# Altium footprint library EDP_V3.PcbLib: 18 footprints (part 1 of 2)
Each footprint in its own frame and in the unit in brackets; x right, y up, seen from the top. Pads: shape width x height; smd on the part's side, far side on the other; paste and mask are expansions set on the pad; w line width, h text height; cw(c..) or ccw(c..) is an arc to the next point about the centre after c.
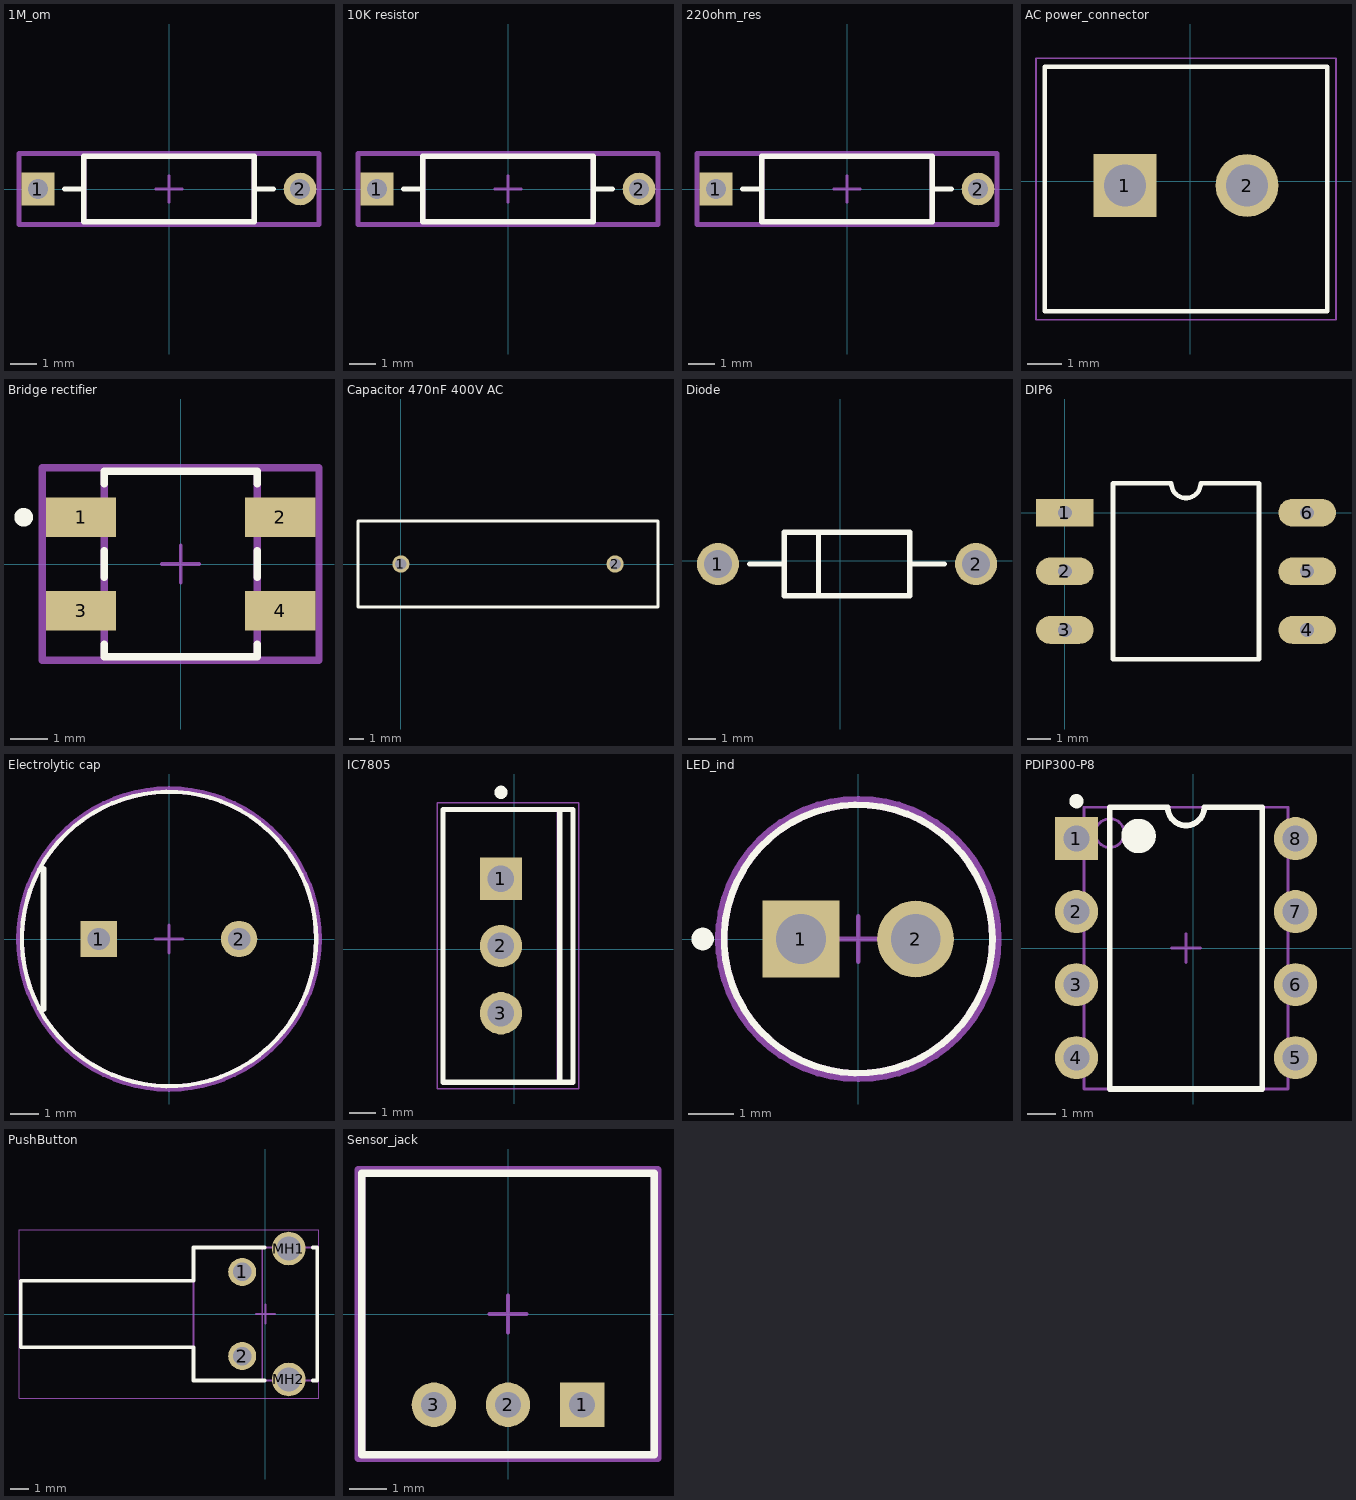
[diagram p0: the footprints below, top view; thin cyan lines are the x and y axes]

## 1M_om [mm]
pads (2):
  rect 1.25x1.25 hole 0.75 paste-2539.97 mask+0: 1(-5,0)
  round 1.25 hole 0.75 paste-2539.97 mask+0: 2(5,0)
Top Overlay:
  lines w0.2: -3.975,0 -3.25,0 ; 3.25,0 3.975,0 ; -3.25,-1.25 3.25,-1.25 3.25,1.25 -3.25,1.25 -3.25,-1.25
Top 3D Body:
  lines w0.2: -3.25,-1.25 3.25,-1.25 3.25,1.25 -3.25,1.25 -3.25,-1.25
Board:
  lines w0.2: -5.725,-1.35 5.725,-1.35 5.725,1.35 -5.725,1.35 -5.725,-1.35
Top Assembly:
  lines w0.2: -5.725,-1.35 5.725,-1.35 5.725,1.35 -5.725,1.35 -5.725,-1.35
Top Component Center:
  lines w0.1: -0.5,0 0.5,0 ; 0,-0.5 0,0.5
3D body "Res_Vishay_MRS25000C1910FCT00_eec.STEP": height 0.25, standoff 0, extent -5.725,-1.35 5.725,1.35

## 3 way switch [mm]

## 10K resistor [mm]
pads (2):
  rect 1.25x1.25 hole 0.75 paste-2539.97 mask+0: 1(-5,0)
  round 1.25 hole 0.75 paste-2539.97 mask+0: 2(5,0)
Top Overlay:
  lines w0.2: -3.975,0 -3.25,0 ; 3.25,0 3.975,0 ; -3.25,-1.25 -3.25,1.25 3.25,1.25 3.25,-1.25 -3.25,-1.25
Top 3D Body:
  lines w0.2: -3.25,-1.25 -3.25,1.25 3.25,1.25 3.25,-1.25 -3.25,-1.25
Board:
  lines w0.2: -5.725,-1.35 -5.725,1.35 5.725,1.35 5.725,-1.35 -5.725,-1.35
Top Assembly:
  lines w0.2: -5.725,-1.35 -5.725,1.35 5.725,1.35 5.725,-1.35 -5.725,-1.35
  text ".Designator" at 0,0.188 h1
Top Component Center:
  lines w0.1: -0.5,0 0.5,0 ; 0,-0.5 0,0.5
3D body "Res_Vishay_MRS25000C1910FCT00_eec.STEP": height 0.25, standoff 0, extent -5.725,-1.35 5.725,1.35

## 220ohm_res [mm]
pads (2):
  rect 1.25x1.25 hole 0.75 paste-2539.97 mask+0: 1(-5,0)
  round 1.25 hole 0.75 paste-2539.97 mask+0: 2(5,0)
Top Overlay:
  lines w0.2: -3.975,0 -3.25,0 ; 3.25,0 3.975,0 ; -3.25,-1.25 3.25,-1.25 3.25,1.25 -3.25,1.25 -3.25,-1.25
Top 3D Body:
  lines w0.2: -3.25,-1.25 3.25,-1.25 3.25,1.25 -3.25,1.25 -3.25,-1.25
Board:
  lines w0.2: -5.725,-1.35 5.725,-1.35 5.725,1.35 -5.725,1.35 -5.725,-1.35
Top Assembly:
  lines w0.2: -5.725,-1.35 5.725,-1.35 5.725,1.35 -5.725,1.35 -5.725,-1.35
Top Component Center:
  lines w0.1: -0.5,0 0.5,0 ; 0,-0.5 0,0.5
3D body "Res_Vishay_MRS25000C1910FCT00_eec.STEP": height 0.25, standoff 0, extent -5.725,-1.35 5.725,1.35

## AC power_connector [mm]
pads (2):
  rect 1.8x1.8 / inner round 1.8 / far side rect 1.8x1.8 hole 1.2: 1(-1.877,-0.127)
  round 1.8 hole 1.2: 2(1.623,-0.127)
Top Overlay:
  lines w0.127: -4.177,-3.727 3.923,-3.727 3.923,3.273 -4.177,3.273 -4.177,-3.727
Mechanical 15:
  lines w0.05: -4.427,-3.977 4.173,-3.977 4.173,3.523 -4.427,3.523 -4.427,-3.977
3D body "step_temp.STEP": height 8.4, standoff -3.8, extent -4.127,-3.627 3.873,3.373

## Bridge rectifier [mm]
pads (4):
  rect 1.875x1.05 smd paste+0 mask+0: 1(-2.658,1.25) 2(2.667,1.25) 3(-2.658,-1.25) 4(2.667,-1.25)
Top Overlay:
  circle w0.25: c-4.195,1.25 r0.125
  lines w0.2: -2.045,-2.15 -2.045,-2.475 2.055,-2.475 2.055,-2.15 ; -2.045,-0.35 -2.045,0.35 ; -2.045,2.15 -2.045,2.475 2.055,2.475 2.055,2.15 ; 2.055,-0.35 2.055,0.35
Top 3D Body:
  lines w0.2: -2.045,-2.475 -2.045,2.475 2.055,2.475 2.055,-2.475 -2.045,-2.475
Board:
  lines w0.2: -3.695,-2.575 -3.695,2.575 3.705,2.575 3.705,-2.575 -3.695,-2.575
Top Assembly:
  lines w0.2: -3.695,-2.575 -3.695,2.575 3.705,2.575 3.705,-2.575 -3.695,-2.575
  text ".Designator" at 0.004,0.188 h1
Top Component Center:
  lines w0.1: -0.495,0 0.504,0 ; 0.005,-0.5 0.005,0.5
3D body "Diode_Diodes_Incorporated_MB10F-13_eec.STEP": height 0.25, standoff 0, extent -3.695,-2.575 3.705,2.575

## Capacitor 470nF 400V AC [mm]
pads (2):
  round 1.2 hole 0.8: 1(0,0) 2(15,0)
Top Overlay:
  lines w0.2: -3,-3 -3,3 0,3 15,3 18,3 18,-3 15,-3 0,-3 -3,-3

## Diode [mm]
pads (2):
  round 1.55 hole 1.05: 1(-4.516,-0.127) 2(5.024,-0.127)
Top Overlay:
  lines w0.2: -3.341,-0.127 -2.071,-0.127 ; -0.801,-1.302 -0.801,1.048 ; 2.579,-0.127 3.849,-0.127 ; -2.071,-1.302 2.579,-1.302 2.579,1.048 -2.071,1.048 -2.071,-1.302

## DIP6 [mm]
pads (6):
  rect 2.5x1.2 hole 0.6: 1(0,0)
  oval 2.5x1.2 hole 0.6: 2(0,-2.54) 3(0,-5.08) 4(10.5,-5.08) 5(10.5,-2.54) 6(10.5,0)
Top Overlay:
  lines w0.2: 2.085,-6.35 8.415,-6.35 8.415,1.27 5.885,1.27 cw(c5.25,1.27) 4.615,1.27 2.085,1.27 2.085,-6.35

## Electrolytic cap [mm]
pads (2):
  rect 1.3x1.3 hole 0.8 paste-2539.97 mask+0: 1(-2.5,0)
  round 1.3 hole 0.8 paste-2539.97 mask+0: 2(2.5,0)
Top Overlay:
  circle w0.15: c0,0 r5.25
  lines w0.2: -4.475,-2.5 -4.475,2.5
Top 3D Body:
  circle w0.15: c0,0 r5.25
Board:
  lines w0.2: -5.35,0 ccw(c0,0) 5.35,0 ccw(c0,0) -5.35,0
Top Assembly:
  text ".Designator" at 0,0.188 h1
Top Component Center:
  lines w0.1: -0.5,0 0.5,0 ; 0,-0.5 0,0.5
3D body "Cap_Panasonic_EEUFR0J182_eec.STEP": height 0.25, standoff 0, extent -5.35,-5.35 5.35,5.35

## IC7805 [mm]
pads (3):
  rect 1.6x1.6 hole 1: 1(-0.508,2.667)
  round 1.6 hole 1: 2(-0.508,0.127) 3(-0.508,-2.413)
Top Overlay:
  circle w0.25: c-0.508,5.927 r0.125
  lines w0.2: 1.707,-5.023 1.707,5.277 ; -2.693,-5.023 -2.693,5.277 2.207,5.277 2.207,-5.023 -2.693,-5.023
Mechanical 13:
  lines w0.1: 1.632,-5.023 1.632,5.277 ; -2.668,-5.023 2.182,-5.023 2.182,5.277 -2.668,5.277 -2.668,-5.023
Mechanical 15:
  lines w0.05: -2.918,-5.273 2.432,-5.273 2.432,5.527 -2.918,5.527 -2.918,-5.273
  lines w0.1: -1.008,0.127 -0.008,0.127 ; -0.508,-0.373 -0.508,0.627
3D body: height 19.68, standoff 18.71, extent 1.632,-4.848 2.182,5.102
3D body: height 17.24, standoff 16.88, extent 1.632,-4.848 2.182,-1.698
3D body: height 17.24, standoff 16.88, extent 1.632,1.952 2.182,5.102
3D body: height 16.88, standoff 16.52, extent 1.632,-4.848 2.182,-1.698
3D body: height 16.88, standoff 16.52, extent 1.632,1.952 2.182,5.102
3D body: height 17.58, standoff 17.24, extent 1.632,-4.848 2.182,-1.663
3D body: height 17.58, standoff 17.24, extent 1.632,1.917 2.182,5.102
3D body: height 16.53, standoff 16.18, extent 1.632,-4.848 2.182,-1.663
3D body: height 16.53, standoff 16.18, extent 1.632,1.917 2.182,5.102
3D body: height 17.9, standoff 17.58, extent 1.632,-4.848 2.182,-1.559
3D body: height 17.9, standoff 17.58, extent 1.632,1.813 2.182,5.102
3D body: height 16.19, standoff 15.87, extent 1.632,-4.848 2.182,-1.559
3D body: height 16.19, standoff 15.87, extent 1.632,1.813 2.182,5.102
3D body: height 18.18, standoff 17.89, extent 1.632,-4.848 2.182,-1.39
3D body: height 18.18, standoff 17.89, extent 1.632,1.644 2.182,5.102
3D body: height 15.87, standoff 15.59, extent 1.632,-4.848 2.182,-1.39
3D body: height 15.87, standoff 15.59, extent 1.632,1.644 2.182,5.102
3D body: height 18.4, standoff 18.17, extent 1.632,-4.848 2.182,-1.163
3D body: height 18.4, standoff 18.17, extent 1.632,1.417 2.182,5.102
3D body: height 15.59, standoff 15.36, extent 1.632,-4.848 2.182,-1.163
3D body: height 15.59, standoff 15.36, extent 1.632,1.417 2.182,5.102
3D body: height 18.57, standoff 18.4, extent 1.632,-4.848 2.182,-0.887
3D body: height 18.57, standoff 18.4, extent 1.632,1.141 2.182,5.102
3D body: height 15.37, standoff 15.19, extent 1.632,-4.848 2.182,-0.887
3D body: height 15.37, standoff 15.19, extent 1.632,1.141 2.182,5.102
3D body: height 18.67, standoff 18.57, extent 1.632,-4.848 2.182,-0.571
3D body: height 18.67, standoff 18.57, extent 1.632,0.825 2.182,5.102
3D body: height 15.2, standoff 15.09, extent 1.632,-4.848 2.182,-0.571
3D body: height 15.2, standoff 15.09, extent 1.632,0.825 2.182,5.102
3D body: height 18.71, standoff 18.67, extent 1.632,-4.848 2.182,-0.229
3D body: height 18.71, standoff 18.67, extent 1.632,0.483 2.182,5.102
3D body: height 15.1, standoff 15.06, extent 1.632,-4.848 2.182,-0.229
3D body: height 15.1, standoff 15.06, extent 1.632,0.483 2.182,5.102
3D body: height 15.06, standoff 13.48, extent 1.632,-4.848 2.182,5.102
3D body: height 13.48, standoff 2.8, extent -2.668,-5.023 2.182,5.277
3D body: height 0, standoff -1.6, extent -0.783,-2.793 -0.233,-2.033
3D body: height 2.8, standoff 0, extent -0.783,-3.083 -0.233,-1.743
3D body: height 0, standoff -1.6, extent -0.783,-0.253 -0.233,0.507
3D body: height 2.8, standoff 0, extent -0.783,-0.543 -0.233,0.797
3D body: height 0, standoff -1.6, extent -0.783,2.287 -0.233,3.047
3D body: height 2.8, standoff 0, extent -0.783,1.997 -0.233,3.337

## LED_ind [mm]
pads (2):
  rect 1.7x1.7 hole 1.1 paste-2539.97 mask+0: 1(-1.27,0)
  round 1.7 hole 1.1 paste-2539.97 mask+0: 2(1.27,0)
Top Overlay:
  circle w0.15: c0,0 r2.975
  circle w0.25: c-3.45,0 r0.125
Top 3D Body:
  circle w0.15: c0,0 r2.975
Board:
  lines w0.2: -3.075,0 cw(c0,0) 3.075,0 cw(c0,0) -3.075,0
Top Assembly:
Top Component Center:
  lines w0.1: -0.5,0 0.5,0 ; 0,-0.5 0,0.5
3D body "Diode_Vishay_Semiconductor_TSFF5210_eec.STEP": height 0.25, standoff 0, extent -3.075,-3.075 3.075,3.075

## On/Off switch [mm]

## PDIP300-P8 [mm] "8-Pin Plastic Dual In-Line Package (PDIP)"
height 5.34
pads (8):
  rect 1.5x1.5 hole 0.9: 1(-4.064,3.81)
  round 1.5 hole 0.9: 2(-4.064,1.27) 3(-4.064,-1.27) 4(-4.064,-3.81) 5(3.556,-3.81) 6(3.556,-1.27) 7(3.556,1.27) 8(3.556,3.81)
Top Overlay:
  circle w0.25: c-4.064,5.11 r0.125
  circle w0.6: c-1.904,3.9 r0.3
  lines w0.2: -2.904,-4.9 -2.904,4.9 -0.889,4.9 ccw(c-0.254,4.9) 0.381,4.9 2.396,4.9 2.396,-4.9 -2.904,-4.9
Mechanical 13:
  circle w0.1: c-2.904,4 r0.5
  lines w0.1: -3.804,-4.9 -3.804,4.9 3.296,4.9 3.296,-4.9 -3.804,-4.9
Mechanical 15:
  lines w0.1: -0.754,0 0.246,0 ; -0.254,-0.5 -0.254,0.5
3D body: height 4.32, standoff 0, extent -3.804,-4.9 3.296,4.9

## PushButton [mm]
pads (4):
  round 1.5 hole 0.99: 1(-1.245,2.25) 2(-1.245,-2.25)
  round 1.8 hole 1.3: MH1(1.245,3.505) MH2(1.245,-3.505)
Top Overlay:
  lines w0.2: -0.054,-3.555 -3.855,-3.555 -3.855,-1.778 -3.858,-1.775 -13.095,-1.775 -13.095,1.775 -3.858,1.775 -3.858,3.552 -3.855,3.555 -0.054,3.555 ; 2.544,-3.555 2.765,-3.555 2.765,3.555 2.544,3.555
Mechanical 13:
  lines w0.1: -3.858,-1.775 -13.095,-1.775 -13.095,1.775 -3.858,1.775 ; -0.175,-3.555 2.765,-3.555 2.765,3.555 -0.175,3.555 ; -0.175,-3.555 -0.175,3.555 ; -0.175,-3.555 -3.855,-3.555 -3.855,3.555 -0.175,3.555
Mechanical 15:
  lines w0.05: -13.195,-4.505 -13.195,4.505 2.865,4.505 2.865,-4.505 -13.195,-4.505
  lines w0.1: -0.5,0 0.5,0 ; 0,-0.5 0,0.5
3D body "c-2-1825027-0-g1-3d.stp": height 7.01, standoff -3.51, extent -13.107,-4.204 2.756,4.204

## Sensor_jack [mm]
pads (3):
  rect 1.2x1.2 hole 0.7 paste-2539.97 mask+0: 1(2,-2.45)
  round 1.2 hole 0.7 paste-2539.97 mask+0: 2(0,-2.45) 3(-2,-2.45)
Top Overlay:
  lines w0.2: -3.95,-3.8 3.95,-3.8 3.95,3.8 -3.95,3.8 -3.95,-3.8
Top 3D Body:
  lines w0.2: -3.95,-3.8 3.95,-3.8 3.95,3.8 -3.95,3.8 -3.95,-3.8
Board:
  lines w0.2: -4.05,-3.9 4.05,-3.9 4.05,3.9 -4.05,3.9 -4.05,-3.9
Top Assembly:
  lines w0.2: -4.05,-3.9 4.05,-3.9 4.05,3.9 -4.05,3.9 -4.05,-3.9
  text ".Designator" at 0,-0.001 h1
Top Component Center:
  lines w0.1: -0.5,0 0.5,0 ; 0,-0.5 0,0.5
3D body "Conn_JST_S3B-PH-K-S_LF_SN_eec.STEP": height 0.25, standoff 0, extent -4.036,-3.937 4.064,3.863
